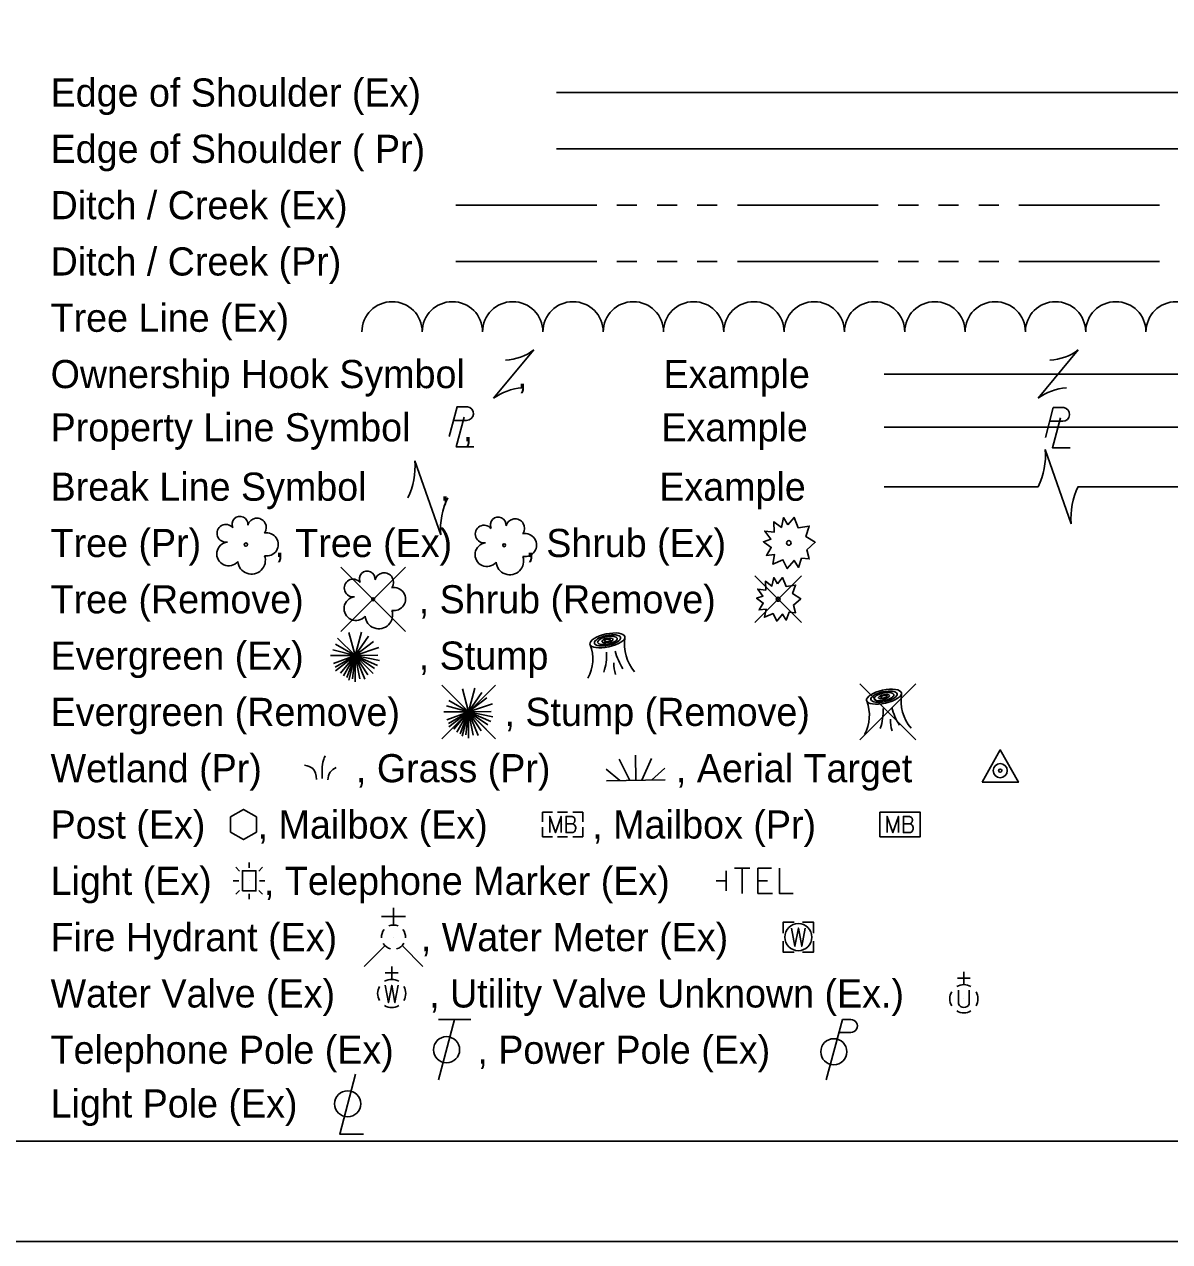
# Model space of a CAD drawing. Extents: x -19 to 40.8, y -1.8 to 26.1.
# Drawn here: x 7.84 to 13.54, y 0 to 6.05 of the extents above; entities that cross this region are included whole.
import ezdxf

# ---------------------------------------------------------------- set-up
doc = ezdxf.new("R2010")
doc.units = 0
for name, color, linetype in [('SH_Border', 7, 'Continuous'), ('SH_Cut_Line', 7, 'Continuous'), ('SH_Text', 7, 'Continuous')]:
    doc.layers.add(name, color=color, linetype=linetype)

msp = doc.modelspace()

# ---------------------------------------------------------------- linework, layer by layer
at = {"layer": 'SH_Border'}
msp.add_lwpolyline([(1.5, 21.5), (33.5, 21.5), (33.5, 0.5), (1.5, 0.5)], close=True, dxfattribs=at)
at = {"layer": 'SH_Cut_Line'}
msp.add_lwpolyline([(0, 0), (34, 0), (34, 22), (0, 22)], close=True, dxfattribs=at)
at = {"layer": 'SH_Text'}
for p, q in [((10.4913, 5.7144), (13.9747, 5.7144)), ((10.4913, 5.4344), (13.9747, 5.4344)), ((9.9909, 5.1544), (10.6909, 5.1544)), ((10.7909, 5.1544), (10.8909, 5.1544)), ((10.9909, 5.1544), (11.0909, 5.1544)), ((11.1909, 5.1544), (11.2909, 5.1544)), ((11.3909, 5.1544), (12.0909, 5.1544)), ((12.1909, 5.1544), (12.2909, 5.1544)), ((12.3909, 5.1544), (12.4909, 5.1544)), ((12.5909, 5.1544), (12.6909, 5.1544)), ((12.7909, 5.1544), (13.4909, 5.1544)), ((9.9909, 4.8744), (10.6909, 4.8744)), ((10.7909, 4.8744), (10.8909, 4.8744)), ((10.9909, 4.8744), (11.0909, 4.8744)), ((11.1909, 4.8744), (11.2909, 4.8744)), ((11.3909, 4.8744), (12.0909, 4.8744)), ((12.1909, 4.8744), (12.2909, 4.8744)), ((12.3909, 4.8744), (12.4909, 4.8744)), ((12.5909, 4.8744), (12.6909, 4.8744)), ((12.7909, 4.8744), (13.4909, 4.8744)), ((10.1782, 4.1944), (10.3782, 4.4344)), ((12.8865, 4.1944), (13.0865, 4.4344)), ((10.2782, 4.3144), (10.2782, 4.3144)), ((12.121, 4.3144), (13.9033, 4.3144)), ((12.9865, 4.3144), (12.9865, 4.3144)), ((9.9785, 4.0834), (10.0434, 4.0834)), ((12.9442, 4.0793), (13.009, 4.0793)), ((10.0186, 4.0522), (10.0186, 4.0522)), ((12.121, 4.0497), (13.9033, 4.0497)), ((12.9842, 4.0481), (12.9842, 4.0481)), ((12.9215, 3.9386), (13.0514, 3.5703)), ((9.7858, 3.8829), (9.9158, 3.5147)), ((12.121, 3.7544), (12.8865, 3.7544)), ((12.9865, 3.7544), (12.9865, 3.7544)), ((13.0864, 3.7544), (13.9033, 3.7544)), ((9.8508, 3.6988), (9.8508, 3.6988)), ((9.4187, 3.3547), (9.7394, 3.0339)), ((9.7394, 3.3547), (9.4187, 3.0339)), ((11.4778, 3.3102), (11.7095, 3.0785)), ((11.7095, 3.3102), (11.4778, 3.0785)), ((9.579, 3.1943), (9.579, 3.1943)), ((11.5936, 3.1944), (11.5936, 3.1944)), ((9.4895, 2.9141), (9.4586, 3.0295)), ((9.4895, 2.9141), (9.5209, 3.0316)), ((9.4895, 2.9141), (9.3918, 2.9716)), ((9.4895, 2.9141), (9.4023, 3.0013)), ((9.4895, 2.9141), (9.5559, 3.0113)), ((9.4895, 2.9141), (9.5809, 2.9843)), ((9.3661, 2.9141), (9.4895, 2.9141)), ((9.4895, 2.9141), (9.3792, 2.9437)), ((9.4895, 2.9141), (9.3823, 2.8751)), ((9.4895, 2.9141), (9.3899, 2.8571)), ((9.4895, 2.9141), (9.3918, 2.8393)), ((9.4895, 2.9141), (9.4159, 2.8275)), ((9.4895, 2.9141), (9.4315, 2.8138)), ((9.4895, 2.9141), (9.4479, 2.8056)), ((9.4895, 2.9141), (9.4579, 2.7927)), ((9.4895, 2.9141), (9.476, 2.7993)), ((9.4895, 2.9141), (9.6079, 2.9543)), ((9.4895, 2.9141), (9.6023, 2.9164)), ((9.4895, 2.7831), (9.4895, 2.9141)), ((9.4895, 2.9141), (9.5125, 2.7982)), ((9.4895, 2.9141), (9.5378, 2.7974)), ((9.4895, 2.9141), (9.5529, 2.8193)), ((9.4895, 2.9141), (9.5792, 2.8261)), ((9.4895, 2.9141), (9.585, 2.8503)), ((9.4895, 2.9141), (9.6011, 2.8656)), ((9.4895, 2.9141), (9.6102, 2.8902)), ((10.7632, 2.9144), (10.7632, 2.9144)), ((9.9199, 2.768), (10.1872, 2.5007)), ((10.1872, 2.768), (9.9199, 2.5007)), ((10.0535, 2.6344), (10.0226, 2.7497)), ((10.0535, 2.6344), (10.0849, 2.7518)), ((10.0535, 2.6344), (10.1199, 2.7315)), ((11.9997, 2.7734), (12.2778, 2.4953)), ((12.2778, 2.7734), (11.9997, 2.4953)), ((10.0535, 2.6344), (9.9432, 2.664)), ((10.0535, 2.6344), (9.9559, 2.6918)), ((10.0535, 2.6344), (9.9663, 2.7215)), ((10.0535, 2.6344), (10.1449, 2.7045)), ((10.0535, 2.6344), (10.1719, 2.6745)), ((9.9301, 2.6344), (10.0535, 2.6344)), ((10.0535, 2.6344), (9.9463, 2.5953)), ((10.0535, 2.6344), (9.9539, 2.5773)), ((10.0535, 2.6344), (9.9559, 2.5595)), ((10.0535, 2.6344), (9.9799, 2.5477)), ((10.0535, 2.6344), (9.9956, 2.534)), ((10.0535, 2.6344), (10.0119, 2.5259)), ((10.0535, 2.6344), (10.0219, 2.513)), ((10.0535, 2.6344), (10.04, 2.5196)), ((10.0535, 2.6344), (10.1663, 2.6367)), ((10.0535, 2.5034), (10.0535, 2.6344)), ((10.0535, 2.6344), (10.0766, 2.5185)), ((10.0535, 2.6344), (10.1019, 2.5177)), ((10.0535, 2.6344), (10.1169, 2.5395)), ((10.0535, 2.6344), (10.1432, 2.5463)), ((10.0535, 2.6344), (10.1491, 2.5705)), ((10.0535, 2.6344), (10.1651, 2.5858)), ((10.0535, 2.6344), (10.1742, 2.6104)), ((10.0535, 2.6344), (10.0535, 2.6344)), ((12.1387, 2.6344), (12.1387, 2.6344)), ((12.1387, 2.6344), (12.1387, 2.6344)), ((10.8552, 2.294), (10.803, 2.4)), ((10.8851, 2.2944), (10.8833, 2.4199)), ((10.9151, 2.2948), (10.9641, 2.4024)), ((10.8065, 2.2932), (10.7381, 2.3503)), ((10.9639, 2.2956), (11.0304, 2.3546)), ((10.739, 2.2922), (11.0312, 2.2965)), ((10.4963, 2.1355), (10.5464, 2.1355)), ((10.5219, 2.0744), (10.5219, 2.0744)), ((12.2, 2.0744), (12.2, 2.0744)), ((10.4963, 2.0133), (10.5464, 2.0133)), ((8.9622, 1.8584), (8.9622, 1.885)), ((8.914, 1.8428), (8.8955, 1.8615)), ((9.0289, 1.8615), (9.0103, 1.8428)), ((11.3349, 1.7444), (11.3349, 1.8444)), ((8.9101, 1.7947), (8.8835, 1.7947)), ((8.9622, 1.7944), (8.9622, 1.7944)), ((9.041, 1.7947), (9.0143, 1.7947)), ((11.3349, 1.7944), (11.2851, 1.7944)), ((8.914, 1.746), (8.8955, 1.7272)), ((8.9622, 1.7304), (8.9622, 1.7038)), ((9.0289, 1.7272), (9.0103, 1.746)), ((9.6802, 1.5745), (9.6802, 1.6605)), ((9.7402, 1.6175), (9.6202, 1.6175)), ((9.6803, 1.5144), (9.6803, 1.5144)), ((9.6803, 1.5144), (9.6803, 1.5144)), ((11.6939, 1.5144), (11.6939, 1.5144)), ((9.638, 1.472), (9.534, 1.368)), ((9.7226, 1.472), (9.8266, 1.368)), ((9.7029, 1.3362), (9.6393, 1.3362)), ((9.6712, 1.3044), (9.6712, 1.368)), ((12.5173, 1.278), (12.5173, 1.3415)), ((12.5491, 1.3097), (12.4855, 1.3097)), ((9.6712, 1.2344), (9.6712, 1.2344)), ((12.4902, 1.2511), (12.4902, 1.1822)), ((12.5444, 1.2511), (12.5444, 1.1822)), ((12.5173, 1.208), (12.5173, 1.208)), ((9.9842, 1.1044), (9.9039, 0.8044)), ((10.0642, 1.1044), (9.9042, 1.1044)), ((11.9132, 1.1044), (11.8329, 0.8044)), ((11.9132, 1.1044), (11.9557, 1.1044)), ((11.8961, 1.0406), (11.9557, 1.0406))]:
    msp.add_line(p, q, dxfattribs=at)
for points in [[(9.9575, 4.0038), (9.9966, 4.152), (10.0483, 4.152)], [(12.9232, 3.9997), (12.9622, 4.1479), (13.0139, 4.1479)], [(10.0319, 4.1002), (9.9924, 3.9524), (10.0797, 3.9524)], [(12.9976, 4.0961), (12.958, 3.9483), (13.0453, 3.9483)], [(11.6424, 3.5649), (11.6726, 3.6016), (11.6934, 3.549), (11.7479, 3.558), (11.731, 3.5074), (11.7783, 3.4776), (11.7354, 3.4409), (11.7479, 3.3952), (11.7103, 3.3986), (11.694, 3.353), (11.6726, 3.3875), (11.6387, 3.3467), (11.6173, 3.391), (11.5663, 3.3695), (11.5759, 3.4166), (11.5353, 3.4125), (11.5589, 3.452), (11.5205, 3.4804), (11.5574, 3.4935), (11.5271, 3.5337), (11.5737, 3.5282), (11.5722, 3.5801), (11.6099, 3.5517), (11.6202, 3.601), (11.6424, 3.5649)], [(11.59, 3.2713), (11.6157, 3.3025), (11.6334, 3.2578), (11.6798, 3.2654), (11.6654, 3.2224), (11.7055, 3.1971), (11.6691, 3.1659), (11.6798, 3.1271), (11.6477, 3.13), (11.6339, 3.0912), (11.6157, 3.1206), (11.5869, 3.0859), (11.5687, 3.1235), (11.5253, 3.1053), (11.5335, 3.1453), (11.499, 3.1417), (11.5191, 3.1753), (11.4865, 3.1995), (11.5178, 3.2107), (11.4921, 3.2448), (11.5317, 3.2401), (11.5304, 3.2843), (11.5624, 3.2601), (11.5712, 3.302), (11.59, 3.2713)], [(8.869, 2.0369), (8.9339, 1.9994), (8.9988, 2.0369), (8.9988, 2.1119), (8.9339, 2.1494), (8.869, 2.1119), (8.869, 2.0369)], [(10.4219, 2.087), (10.4219, 2.1355), (10.4704, 2.1355)], [(10.5722, 2.1355), (10.6219, 2.1355), (10.6219, 2.087)], [(10.4704, 2.0133), (10.4219, 2.0133), (10.4219, 2.0618)], [(10.4571, 2.0344), (10.4571, 2.1144), (10.486, 2.0344), (10.5137, 2.1144), (10.5137, 2.0344)], [(10.573, 2.0778), (10.5761, 2.081), (10.578, 2.0829), (10.5793, 2.0848), (10.5799, 2.086), (10.5811, 2.0885), (10.5818, 2.0904), (10.583, 2.0948), (10.583, 2.0967), (10.583, 2.0993), (10.5824, 2.103), (10.5811, 2.1062), (10.5793, 2.1087), (10.5761, 2.1112), (10.5736, 2.1125), (10.5723, 2.1131), (10.5692, 2.1144), (10.5383, 2.1144), (10.5383, 2.0344), (10.573, 2.0344), (10.5774, 2.0369), (10.5811, 2.04), (10.5843, 2.0451), (10.5862, 2.0507), (10.5868, 2.0564), (10.5868, 2.0602), (10.5856, 2.064), (10.583, 2.0696), (10.5799, 2.0734), (10.573, 2.0778), (10.5383, 2.0778)], [(10.6219, 2.0618), (10.6219, 2.0133), (10.5722, 2.0133)], [(12.1352, 2.0344), (12.1352, 2.1144), (12.1642, 2.0344), (12.1919, 2.1144), (12.1919, 2.0344)], [(12.2511, 2.0778), (12.2542, 2.081), (12.2561, 2.0829), (12.2574, 2.0848), (12.258, 2.086), (12.2593, 2.0885), (12.2599, 2.0904), (12.2612, 2.0948), (12.2612, 2.0967), (12.2612, 2.0993), (12.2605, 2.103), (12.2593, 2.1062), (12.2574, 2.1087), (12.2542, 2.1112), (12.2517, 2.1125), (12.2505, 2.1131), (12.2473, 2.1144), (12.2164, 2.1144), (12.2164, 2.0344), (12.2511, 2.0344), (12.2555, 2.0369), (12.2593, 2.04), (12.2624, 2.0451), (12.2643, 2.0507), (12.2649, 2.0564), (12.2649, 2.0602), (12.2637, 2.064), (12.2612, 2.0696), (12.258, 2.0734), (12.2511, 2.0778), (12.2164, 2.0778)], [(11.3757, 1.8565), (11.4534, 1.8565)], [(11.415, 1.8565), (11.415, 1.7315)], [(11.5607, 1.8565), (11.4928, 1.8565), (11.4928, 1.7315), (11.5656, 1.7315)], [(11.6001, 1.8565), (11.6001, 1.7315), (11.668, 1.7315)], [(11.4928, 1.7944), (11.541, 1.7944)], [(11.6739, 1.5894), (11.6189, 1.5894), (11.6189, 1.5344)], [(11.7689, 1.5344), (11.7689, 1.5894), (11.7139, 1.5894)], [(11.6606, 1.5594), (11.6772, 1.4694), (11.6939, 1.5594), (11.7106, 1.4694), (11.7272, 1.5594)], [(11.6189, 1.4944), (11.6189, 1.4394), (11.6739, 1.4394)], [(11.7139, 1.4394), (11.7689, 1.4394), (11.7689, 1.4944)], [(9.6393, 1.2754), (9.6553, 1.1892), (9.6712, 1.2754), (9.6872, 1.1892), (9.703, 1.2754)], [(9.4915, 0.8331), (9.4127, 0.5339), (9.5309, 0.5339)]]:
    msp.add_lwpolyline(points, dxfattribs=at)
for points in [[(12.6082, 2.2844), (12.7882, 2.2844), (12.6982, 2.4454)], [(12.1, 2.1355), (12.3, 2.1355), (12.3, 2.0133), (12.1, 2.0133)], [(8.9289, 1.7444), (8.9955, 1.7444), (8.9955, 1.8444), (8.9289, 1.8444)]]:
    msp.add_lwpolyline(points, close=True, dxfattribs=at)
for centre, radius in [((8.946, 3.4663), 0.0084), ((10.2306, 3.4628), 0.0072), ((11.6466, 3.4744), 0.0115), ((9.579, 3.1943), 0.0072), ((11.5936, 3.1944), 0.00979), ((12.6982, 2.3422), 0.035), ((12.6982, 2.3422), 0.008), ((11.6939, 1.5144), 0.0675), ((9.944, 0.9544), 0.065), ((11.8704, 0.9444), 0.065), ((9.4521, 0.6854), 0.065)]:
    msp.add_circle(centre, radius, dxfattribs=at)
for centre, radius, start, end in [((9.6732, 4.5243), 0.15, 0.00982, 179.99264), ((9.9732, 4.5243), 0.15, 0.00982, 179.99264), ((10.2732, 4.5243), 0.15, 0.00982, 179.99264), ((10.5732, 4.5243), 0.15, 0.00982, 179.99264), ((10.8732, 4.5243), 0.15, 0.00982, 179.99264), ((11.1732, 4.5243), 0.15, 0.00982, 179.99264), ((11.4732, 4.5243), 0.15, 0.00982, 179.99264), ((11.7732, 4.5243), 0.15, 0.00982, 179.99264), ((12.0732, 4.5243), 0.15, 0.00982, 179.99264), ((12.3732, 4.5243), 0.15, 0.00982, 179.99264), ((12.6732, 4.5243), 0.15, 0.00982, 179.99264), ((12.9732, 4.5243), 0.15, 0.00982, 179.99264), ((13.2732, 4.5243), 0.15, 0.00982, 179.99264), ((13.5732, 4.5243), 0.15, 0.00982, 179.99264), ((10.2201, 4.6493), 0.2668, 273.69448, 306.33701), ((12.9283, 4.6493), 0.2668, 273.69448, 306.33701), ((10.3363, 3.9794), 0.2668, 93.69448, 126.33701), ((13.0446, 3.9794), 0.2668, 93.69448, 126.33701), ((10.0431, 4.1179), 0.0345, 270.47098, 81.3281), ((13.0087, 4.1138), 0.0345, 270.47098, 81.3281), ((12.5895, 3.9061), 0.3335, 332.94224, 5.58476), ((9.4539, 3.8505), 0.3335, 332.94224, 5.58476), ((13.3834, 3.6028), 0.3335, 152.94224, 185.58476), ((10.2478, 3.5471), 0.3335, 152.94224, 185.58476), ((8.9165, 3.5673), 0.0395, 354.0047, 205.97412), ((9.0008, 3.5511), 0.0466, 323.82996, 165.0376), ((10.2011, 3.5638), 0.0395, 354.0047, 205.97412), ((10.2854, 3.5477), 0.0466, 323.82996, 165.0376), ((8.8467, 3.5222), 0.0441, 39.06254, 279.54124), ((9.0498, 3.4673), 0.0574, 259.14531, 101.45961), ((10.1313, 3.5187), 0.0441, 39.06254, 279.54124), ((10.3344, 3.4639), 0.0574, 259.14531, 101.45961), ((8.8604, 3.4198), 0.0592, 96.17219, 320.57371), ((10.145, 3.4163), 0.0592, 96.17219, 320.57371), ((8.9744, 3.3881), 0.0685, 184.94757, 19.45715), ((10.259, 3.3847), 0.0685, 184.94757, 19.45715), ((9.5495, 3.2954), 0.0395, 354.0047, 205.97412), ((9.4797, 3.2503), 0.0441, 39.06254, 279.54124), ((9.6338, 3.2792), 0.0466, 323.82996, 165.0376), ((9.6828, 3.1954), 0.0574, 259.14531, 101.45961), ((9.4934, 3.1479), 0.0592, 96.17219, 320.57371), ((9.6074, 3.1162), 0.0685, 184.94757, 19.45715), ((10.4716, 2.8971), 0.2001, 331.53375, 20.92689), ((11.0434, 2.9714), 0.2146, 171.41061, 219.91939), ((10.4873, 2.9156), 0.2527, 340.79377, 3.54808), ((11.0885, 3.0172), 0.316, 194.9653, 212.12159), ((10.9584, 2.8744), 0.1819, 178.79264, 197.12241), ((11.8472, 2.6171), 0.2001, 331.53375, 20.92689), ((12.419, 2.6914), 0.2146, 171.41061, 219.91939), ((11.8629, 2.6356), 0.2527, 340.79377, 3.54808), ((12.4641, 2.7372), 0.316, 194.9653, 212.12159), ((12.334, 2.5944), 0.1819, 178.79264, 197.12241), ((9.6803, 1.5144), 0.06, 68.13946, 112.03798), ((9.6803, 1.5144), 0.06, 140.02099, 184.06293), ((9.6803, 1.5144), 0.06, 356.01648, 39.98885), ((9.6803, 1.5144), 0.06, 211.87877, 255.84793), ((9.6803, 1.5144), 0.06, 283.82389, 329.90967), ((9.6712, 1.2344), 0.07, 60.01836, 120.01574), ((12.5173, 1.208), 0.07, 60.01836, 120.01574), ((9.6712, 1.2344), 0.07, 150.01836, 209.98164), ((9.6712, 1.2344), 0.07, 330.01836, 29.98164), ((12.5173, 1.208), 0.07, 150.01836, 209.98164), ((12.5173, 1.208), 0.07, 330.01836, 29.98164), ((9.6712, 1.2344), 0.07, 239.98426, 299.98164), ((12.5173, 1.1949), 0.03, 205.19243, 334.80757), ((11.9563, 1.0725), 0.0319, 268.8767, 91.1233), ((12.5173, 1.208), 0.07, 239.98426, 299.98164)]:
    msp.add_arc(centre, radius, start, end, dxfattribs=at)
for centre, major_axis in [((10.7444, 2.9899), (0.0868, 0.0187)), ((10.7444, 2.9899), (0.0651, 0.0141)), ((10.7444, 2.9899), (0.0488, 0.0105)), ((10.7444, 2.9899), (0.0275, 0.0059)), ((10.7444, 2.9899), (0.0154, 0.0033)), ((12.12, 2.7099), (0.0868, 0.0187)), ((12.12, 2.7099), (0.0651, 0.0141)), ((12.12, 2.7099), (0.0488, 0.0105)), ((12.12, 2.7099), (0.0275, 0.0059)), ((12.12, 2.7099), (0.0154, 0.0033))]:
    msp.add_ellipse(centre, major_axis=major_axis, ratio=0.36865, dxfattribs=at)
for points in [[(9.2382, 2.3699), (9.2797, 2.3523), (9.2974, 2.2989)], [(9.3256, 2.3029), (9.3256, 2.3503), (9.3315, 2.3947), (9.3403, 2.4154)], [(9.3533, 2.2958), (9.3652, 2.3342), (9.3947, 2.3579)]]:
    msp.add_spline(points, degree=3, dxfattribs=at)

# ---------------------------------------------------------------- texts
for s, p in [('Edge of Shoulder (Ex)', (7.9747, 5.6444)), ('Edge of Shoulder ( Pr)', (7.9747, 5.3644)), ('Ditch / Creek (Ex)', (7.9747, 5.0844)), ('Ditch / Creek (Pr)', (7.9747, 4.8044)), ('Tree Line (Ex)', (7.9747, 4.5244)), ('Ownership Hook Symbol     ,             Example', (7.9747, 4.2444)), ('Property Line Symbol     ,                  Example', (7.9747, 3.9797)), ('Break Line Symbol       ,                    Example', (7.9747, 3.6844)), ('Tree (Pr)       , Tree (Ex)       , Shrub (Ex)', (7.9747, 3.4044)), ('Tree (Remove)           , Shrub (Remove)', (7.9747, 3.1244)), ('Evergreen (Ex)           , Stump ', (7.9747, 2.8444)), ('Evergreen (Remove)          , Stump (Remove)', (7.9747, 2.5644)), ('Wetland (Pr)         , Grass (Pr)            , Aerial Target    ', (7.9747, 2.2844)), ('Post (Ex)     , Mailbox (Ex)          , Mailbox (Pr)', (7.9747, 2.0044)), ('Light (Ex)     , Telephone Marker (Ex)     ', (7.9747, 1.7244)), ('Fire Hydrant (Ex)        , Water Meter (Ex)', (7.9747, 1.4444)), ('Water Valve (Ex)         , Utility Valve Unknown (Ex.)', (7.9747, 1.1644)), ('Telephone Pole (Ex)        , Power Pole (Ex)', (7.9747, 0.8844)), ('Light Pole (Ex)     ', (7.9747, 0.6173))]:
    msp.add_text(s, height=0.14, dxfattribs=at).set_placement(p)

doc.saveas('drawing.dxf')
